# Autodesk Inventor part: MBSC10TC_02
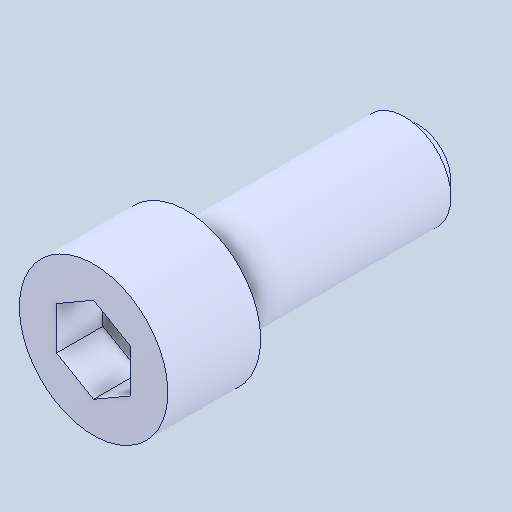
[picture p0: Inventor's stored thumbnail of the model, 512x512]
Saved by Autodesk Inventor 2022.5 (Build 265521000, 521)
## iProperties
Created: 2024-05
Part Number: MBSC10TC_02
Material: 一般
Document SubType Name: Modeling
Designer: ImaoCorp
Density: 1 g/cm^3
Appearance: 既定
Author: ImaoCorp
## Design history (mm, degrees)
feature "MBSC10TC_02"
node "ソリッド1"
